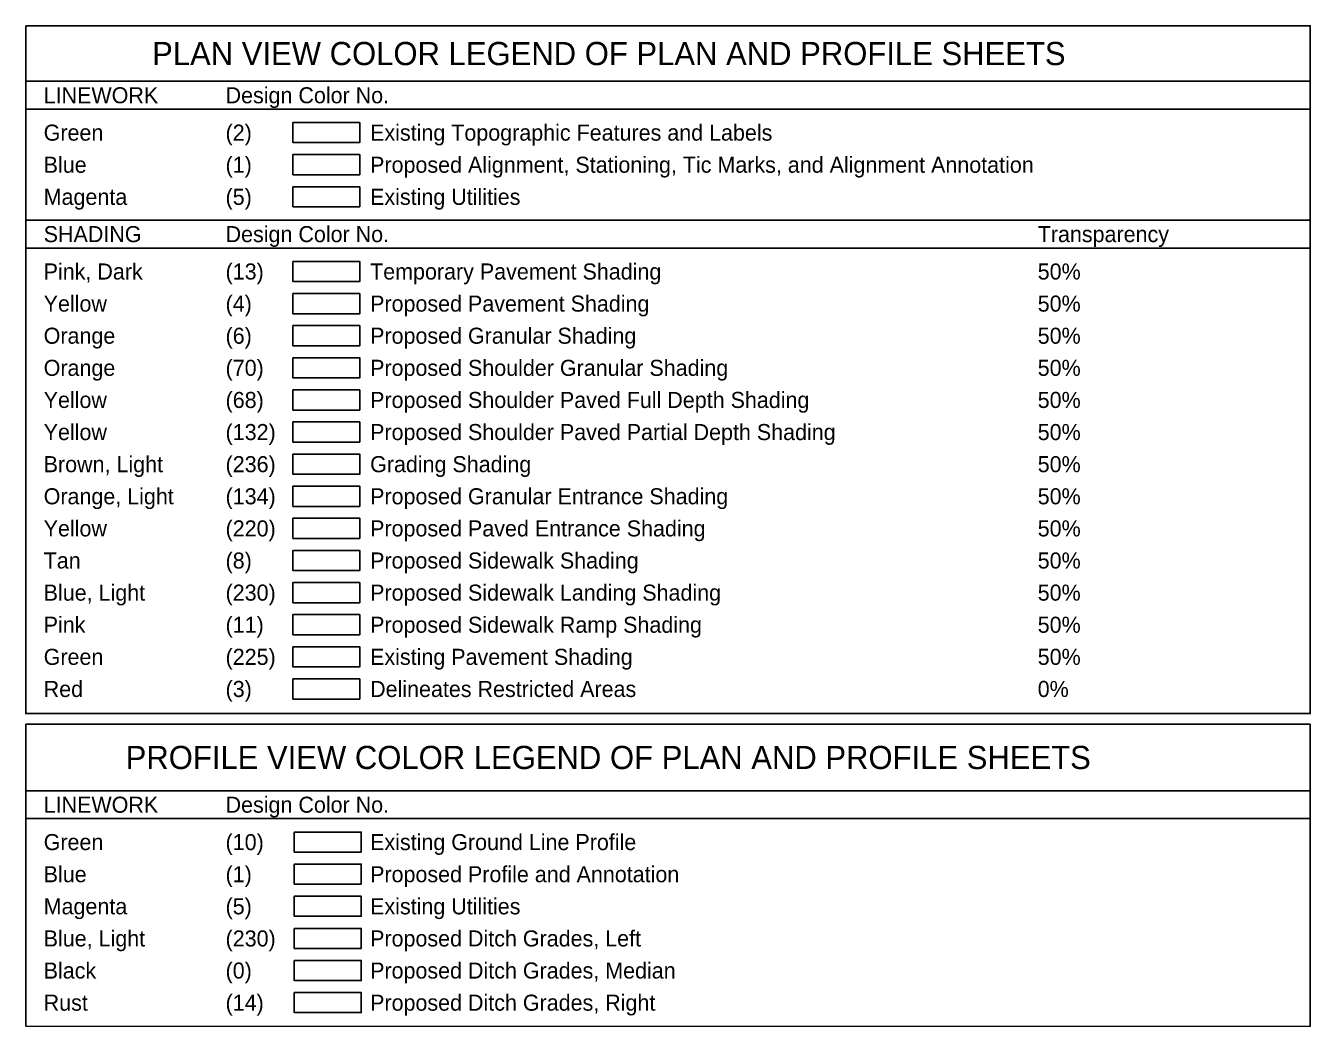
# Model space of a CAD drawing. Extents: x 0.53 to 2.71, y 0.07 to 1.78.
# Drawn here: x 1.712 to 2.712, y 0.999 to 1.778 of the extents above; entities that cross this region are included whole.
import ezdxf

# ---------------------------------------------------------------- set-up
doc = ezdxf.new("R2010")
doc.units = 0
for name, color, linetype in [('Alignment', 7, 'Continuous'), ('dsnProfileDitchGradePropLeft', 7, 'Continuous'), ('dsnProfileDitchGradePropMed', 7, 'Continuous'), ('dsnProfileDitchGradePropRight', 7, 'Continuous'), ('dsnTextFinalPlan', 7, 'Continuous'), ('dsnTextShtTitle', 7, 'Continuous'), ('phoEdgeCurb', 7, 'Continuous'), ('PhoUtility', 7, 'Continuous'), ('Shape', 7, 'Continuous'), ('SheetText', 7, 'Continuous'), ('Terrain', 7, 'Continuous'), ('Text', 7, 'Continuous')]:
    doc.layers.add(name, color=color, linetype=linetype)

msp = doc.modelspace()

# ---------------------------------------------------------------- linework, layer by layer
at = {"layer": 'Alignment'}
for points in [[(1.9204, 1.6771), (1.9725, 1.6771), (1.9725, 1.6615), (1.9204, 1.6615)], [(1.9215, 1.1248), (1.9736, 1.1248), (1.9736, 1.1092), (1.9215, 1.1092)]]:
    msp.add_lwpolyline(points, close=True, dxfattribs=at)
at = {"layer": 'dsnProfileDitchGradePropLeft'}
msp.add_lwpolyline([(1.9215, 1.0748), (1.9736, 1.0748), (1.9736, 1.0592), (1.9215, 1.0592)], close=True, dxfattribs=at)
at = {"layer": 'dsnProfileDitchGradePropMed'}
msp.add_lwpolyline([(1.9215, 1.0498), (1.9736, 1.0498), (1.9736, 1.0342), (1.9215, 1.0342)], close=True, dxfattribs=at)
at = {"layer": 'dsnProfileDitchGradePropRight'}
msp.add_lwpolyline([(1.9215, 1.0248), (1.9736, 1.0248), (1.9736, 1.0092), (1.9215, 1.0092)], close=True, dxfattribs=at)
at = {"layer": 'dsnTextFinalPlan'}
for p, q in [((1.7124, 1.7342), (2.7124, 1.7342)), ((1.7124, 1.7125), (2.7124, 1.7125)), ((1.7124, 1.626), (2.7124, 1.626)), ((1.7124, 1.6044), (2.7124, 1.6044)), ((1.7124, 1.1819), (2.7124, 1.1819)), ((1.7124, 1.1602), (2.7124, 1.1602))]:
    msp.add_line(p, q, dxfattribs=at)
at = {"layer": 'dsnTextShtTitle'}
for p, q in [((1.7124, 0.9987), (1.7124, 1.2337)), ((1.7124, 1.2337), (2.7124, 1.2337)), ((2.7124, 1.2337), (2.7124, 0.9985)), ((2.7124, 0.9985), (1.7124, 0.9987))]:
    msp.add_line(p, q, dxfattribs=at)
msp.add_lwpolyline([(1.7124, 1.7775), (2.7124, 1.7775), (2.7124, 1.242), (1.7124, 1.242)], close=True, dxfattribs=at)
at = {"layer": 'phoEdgeCurb'}
msp.add_lwpolyline([(1.9204, 1.7021), (1.9725, 1.7021), (1.9725, 1.6865), (1.9204, 1.6865)], close=True, dxfattribs=at)
at = {"layer": 'PhoUtility'}
for points in [[(1.9204, 1.6521), (1.9725, 1.6521), (1.9725, 1.6365), (1.9204, 1.6365)], [(1.9215, 1.0998), (1.9736, 1.0998), (1.9736, 1.0842), (1.9215, 1.0842)]]:
    msp.add_lwpolyline(points, close=True, dxfattribs=at)
at = {"layer": 'Shape'}
for points in [[(1.9204, 1.594), (1.9725, 1.594), (1.9725, 1.5783), (1.9204, 1.5783)], [(1.9204, 1.569), (1.9725, 1.569), (1.9725, 1.5533), (1.9204, 1.5533)], [(1.9204, 1.544), (1.9725, 1.544), (1.9725, 1.5283), (1.9204, 1.5283)], [(1.9204, 1.519), (1.9725, 1.519), (1.9725, 1.5033), (1.9204, 1.5033)], [(1.9204, 1.494), (1.9725, 1.494), (1.9725, 1.4783), (1.9204, 1.4783)], [(1.9204, 1.469), (1.9725, 1.469), (1.9725, 1.4533), (1.9204, 1.4533)], [(1.9204, 1.444), (1.9725, 1.444), (1.9725, 1.4283), (1.9204, 1.4283)], [(1.9204, 1.419), (1.9725, 1.419), (1.9725, 1.4033), (1.9204, 1.4033)], [(1.9204, 1.394), (1.9725, 1.394), (1.9725, 1.3783), (1.9204, 1.3783)], [(1.9204, 1.369), (1.9725, 1.369), (1.9725, 1.3533), (1.9204, 1.3533)], [(1.9204, 1.344), (1.9725, 1.344), (1.9725, 1.3283), (1.9204, 1.3283)], [(1.9204, 1.319), (1.9725, 1.319), (1.9725, 1.3033), (1.9204, 1.3033)], [(1.9204, 1.294), (1.9725, 1.294), (1.9725, 1.2783), (1.9204, 1.2783)], [(1.9204, 1.269), (1.9725, 1.269), (1.9725, 1.2533), (1.9204, 1.2533)]]:
    msp.add_lwpolyline(points, close=True, dxfattribs=at)
at = {"layer": 'Terrain'}
msp.add_lwpolyline([(1.9215, 1.1498), (1.9736, 1.1498), (1.9736, 1.1342), (1.9215, 1.1342)], close=True, dxfattribs=at)

# ---------------------------------------------------------------- texts
at = {"layer": 'SheetText'}
for s, p in [('Transparency', (2.5002, 1.609)), ('50%', (2.5002, 1.5799)), ('50%', (2.5002, 1.5549)), ('50%', (2.5002, 1.5299)), ('50%', (2.5002, 1.5049)), ('50%', (2.5002, 1.4799)), ('50%', (2.5002, 1.4549)), ('50%', (2.5002, 1.4299)), ('50%', (2.5002, 1.4049)), ('50%', (2.5002, 1.3799)), ('50%', (2.5002, 1.3549)), ('50%', (2.5002, 1.3299)), ('50%', (2.5002, 1.3049)), ('50%', (2.5002, 1.2799)), ('0%', (2.5002, 1.2549))]:
    msp.add_text(s, height=0.0125, dxfattribs=at).set_placement(p)
at = {"layer": 'Text'}
for s, height, p in [('PLAN VIEW COLOR LEGEND OF PLAN AND PROFILE SHEETS', 0.018056, (1.8108, 1.7468)), ('Design Color No.', 0.0125, (1.868, 1.7171)), ('LINEWORK', 0.0125, (1.7264, 1.7171)), ('Green', 0.0125, (1.7264, 1.688)), ('(2) ', 0.0125, (1.868, 1.688)), ('Existing Topographic Features and Labels', 0.0125, (1.9805, 1.688)), ('Blue ', 0.0125, (1.7264, 1.663)), ('(1) ', 0.0125, (1.868, 1.663)), ('Proposed Alignment, Stationing, Tic Marks, and Alignment Annotation ', 0.0125, (1.9805, 1.663)), ('Magenta', 0.0125, (1.7264, 1.638)), ('(5) ', 0.0125, (1.868, 1.638)), ('Existing Utilities ', 0.0125, (1.9805, 1.638)), ('SHADING', 0.0125, (1.7264, 1.609)), ('Design Color No.', 0.0125, (1.868, 1.609)), ('Pink, Dark', 0.0125, (1.7264, 1.5799)), ('(13) ', 0.0125, (1.868, 1.5799)), ('Temporary Pavement Shading', 0.0125, (1.9805, 1.5799)), ('Yellow', 0.0125, (1.7264, 1.5549)), ('(4) ', 0.0125, (1.868, 1.5549)), ('Proposed Pavement Shading', 0.0125, (1.9805, 1.5549)), ('Orange', 0.0125, (1.7264, 1.5299)), ('(6) ', 0.0125, (1.868, 1.5299)), ('Proposed Granular Shading', 0.0125, (1.9805, 1.5299)), ('Orange', 0.0125, (1.7264, 1.5049)), ('(70) ', 0.0125, (1.868, 1.5049)), ('Proposed Shoulder Granular Shading', 0.0125, (1.9805, 1.5049)), ('Yellow', 0.0125, (1.7264, 1.4799)), ('(68) ', 0.0125, (1.868, 1.4799)), ('Proposed Shoulder Paved Full Depth Shading', 0.0125, (1.9805, 1.4799)), ('Yellow', 0.0125, (1.7264, 1.4549)), ('(132) ', 0.0125, (1.868, 1.4549)), ('Proposed Shoulder Paved Partial Depth Shading', 0.0125, (1.9805, 1.4549)), ('Brown, Light', 0.0125, (1.7264, 1.4299)), ('(236) ', 0.0125, (1.868, 1.4299)), ('Grading Shading', 0.0125, (1.9805, 1.4299)), ('Orange, Light', 0.0125, (1.7264, 1.4049)), ('(134) ', 0.0125, (1.868, 1.4049)), ('Proposed Granular Entrance Shading', 0.0125, (1.9805, 1.4049)), ('Yellow', 0.0125, (1.7264, 1.3799)), ('(220) ', 0.0125, (1.868, 1.3799)), ('Proposed Paved Entrance Shading', 0.0125, (1.9805, 1.3799)), ('Tan', 0.0125, (1.7264, 1.3549)), ('(8) ', 0.0125, (1.868, 1.3549)), ('Proposed Sidewalk Shading', 0.0125, (1.9805, 1.3549)), ('Blue, Light', 0.0125, (1.7264, 1.3299)), ('(230) ', 0.0125, (1.868, 1.3299)), ('Proposed Sidewalk Landing Shading', 0.0125, (1.9805, 1.3299)), ('Pink', 0.0125, (1.7264, 1.3049)), ('(11) ', 0.0125, (1.868, 1.3049)), ('Proposed Sidewalk Ramp Shading', 0.0125, (1.9805, 1.3049)), ('Green', 0.0125, (1.7264, 1.2799)), ('(225) ', 0.0125, (1.868, 1.2799)), ('Existing Pavement Shading', 0.0125, (1.9805, 1.2799)), ('Red', 0.0125, (1.7264, 1.2549)), ('(3) ', 0.0125, (1.868, 1.2549)), ('Delineates Restricted Areas', 0.0125, (1.9805, 1.2549)), ('PROFILE VIEW COLOR LEGEND OF PLAN AND PROFILE SHEETS', 0.018056, (1.7902, 1.1988)), ('LINEWORK', 0.0125, (1.7264, 1.1648)), ('Design Color No.', 0.0125, (1.868, 1.1648)), ('Green ', 0.0125, (1.7264, 1.1357)), ('(10) ', 0.0125, (1.868, 1.1357)), ('Existing Ground Line Profile ', 0.0125, (1.9805, 1.1357)), ('Blue', 0.0125, (1.7264, 1.1107)), ('(1) ', 0.0125, (1.868, 1.1107)), ('Proposed Profile and Annotation ', 0.0125, (1.9805, 1.1107)), ('Magenta ', 0.0125, (1.7264, 1.0857)), ('(5) ', 0.0125, (1.868, 1.0857)), ('Existing Utilities ', 0.0125, (1.9805, 1.0857)), ('Blue, Light', 0.0125, (1.7264, 1.0607)), ('(230) ', 0.0125, (1.868, 1.0607)), ('Proposed Ditch Grades, Left ', 0.0125, (1.9805, 1.0607)), ('Black', 0.0125, (1.7264, 1.0357)), ('(0) ', 0.0125, (1.868, 1.0357)), ('Proposed Ditch Grades, Median ', 0.0125, (1.9805, 1.0357)), ('Rust ', 0.0125, (1.7264, 1.0107)), ('(14) ', 0.0125, (1.868, 1.0107)), ('Proposed Ditch Grades, Right ', 0.0125, (1.9805, 1.0107))]:
    msp.add_text(s, height=height, dxfattribs=at).set_placement(p)

doc.saveas('drawing.dxf')
